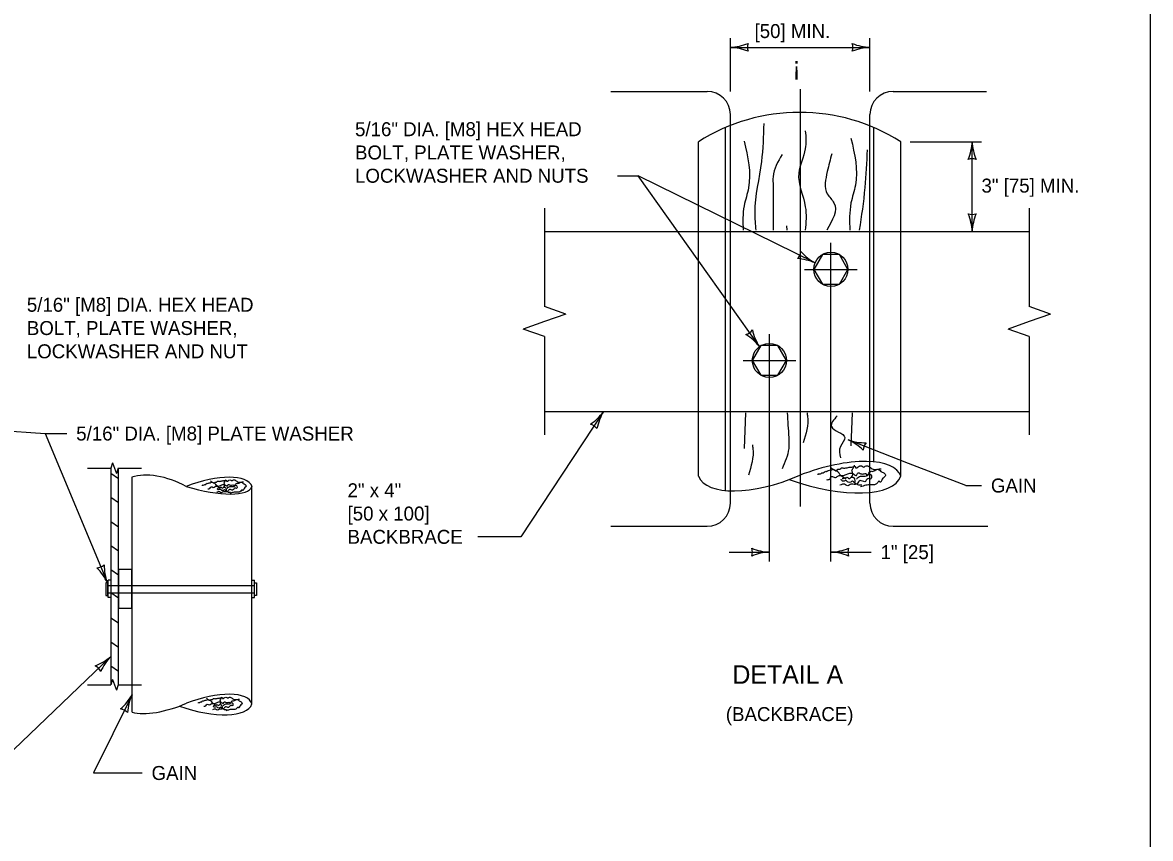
# Model space of a CAD drawing. Extents: x 49991.4 to 50021, y 49987.6 to 50011.4.
# Drawn here: x 50003.769 to 50008.615, y 50003.747 to 50007.252 of the extents above; entities that cross this region are included whole.
import ezdxf

# ---------------------------------------------------------------- set-up
doc = ezdxf.new("R2010")
doc.units = 0
for name, color, linetype in [('Level 1', 7, 'Continuous'), ('Level 2', 7, 'Continuous'), ('Level 3', 7, 'Continuous'), ('Level 4', 7, 'Continuous'), ('Level 5', 7, 'Continuous'), ('Level 6', 7, 'Continuous')]:
    doc.layers.add(name, color=color, linetype=linetype)

msp = doc.modelspace()

# ---------------------------------------------------------------- linework, layer by layer
at = {"layer": 'Level 1'}
for p, q in [((50006.7885, 50006.3548), (50006.7885, 50006.8013)), ((50007.4262, 50006.3548), (50007.4262, 50006.8013)), ((50006.6728, 50006.3548), (50006.6728, 50006.7405)), ((50007.5419, 50006.3548), (50007.5419, 50006.7405)), ((50006.0112, 50006.3548), (50008.0941, 50006.3548)), ((50007.0509, 50006.3792), (50007.0525, 50006.3597)), ((50006.0112, 50005.5805), (50008.0941, 50005.5805)), ((50006.6728, 50005.3029), (50006.6728, 50005.5805)), ((50006.7885, 50005.2434), (50006.7885, 50005.5805)), ((50007.4262, 50005.3653), (50007.4262, 50005.5805)), ((50007.5419, 50005.3029), (50007.5419, 50005.5805)), ((50006.875, 50005.5756), (50006.8691, 50005.4216)), ((50007.3338, 50005.5756), (50007.3281, 50005.4335)), ((50004.1807, 50005.2918), (50004.1482, 50005.3146)), ((50004.1807, 50004.8266), (50004.1807, 50005.3125)), ((50004.2394, 50004.2893), (50004.2394, 50005.2987)), ((50004.7548, 50004.6204), (50004.7548, 50005.2591)), ((50004.1807, 50005.1883), (50004.1482, 50005.2111)), ((50004.1807, 50005.0849), (50004.1482, 50005.1077)), ((50004.1807, 50004.9814), (50004.1482, 50005.0042)), ((50004.181, 50004.8778), (50004.1482, 50004.9008)), ((50004.1363, 50004.7815), (50004.1363, 50004.8567)), ((50004.1468, 50004.8567), (50004.1363, 50004.8567)), ((50004.7548, 50004.8567), (50004.7653, 50004.8567)), ((50004.7653, 50004.7815), (50004.7653, 50004.8567)), ((50004.1468, 50004.7815), (50004.1363, 50004.7815)), ((50004.181, 50004.7792), (50004.1481, 50004.8023)), ((50004.7548, 50004.7815), (50004.7653, 50004.7815)), ((50004.1807, 50004.6711), (50004.1482, 50004.6939)), ((50004.7548, 50004.3245), (50004.7548, 50004.6204)), ((50004.1807, 50004.5676), (50004.1482, 50004.5904)), ((50004.1807, 50004.4642), (50004.1482, 50004.487))]:
    msp.add_line(p, q, dxfattribs=at)
for points in [[(50008.6146, 50011.2628), (50000.3356, 50011.2628), (50000.3356, 50000.0624), (50008.6146, 50000.0624)], [(50007.3153, 50006.1917), (50007.2786, 50006.2554), (50007.2051, 50006.2554), (50007.1683, 50006.1917), (50007.2051, 50006.128), (50007.2786, 50006.128)], [(50007.0513, 50005.8004), (50007.0145, 50005.8641), (50006.9411, 50005.8641), (50006.9043, 50005.8004), (50006.9411, 50005.7367), (50007.0145, 50005.7367)], [(50004.2387, 50004.7369), (50004.2387, 50004.9027), (50004.181, 50004.9027), (50004.181, 50004.7369)], [(50004.1355, 50004.8456), (50004.127, 50004.8456), (50004.127, 50004.791), (50004.1355, 50004.791)], [(50004.7661, 50004.8456), (50004.7746, 50004.8456), (50004.7746, 50004.791), (50004.7661, 50004.791)]]:
    msp.add_lwpolyline(points, close=True, dxfattribs=at)
for points in [[(50004.1481, 50005.3374), (50004.1481, 50004.4066)], [(50004.1807, 50004.4066), (50004.1807, 50005.3374)]]:
    msp.add_lwpolyline(points, dxfattribs=at)
for centre in [(50007.2418, 50006.1917), (50006.9778, 50005.8004)]:
    msp.add_circle(centre, 0.0735, dxfattribs=at)
msp.add_arc((50007.1073, 50006.0536), 0.8128, 57.6815, 122.3185, dxfattribs=at)
for centre, major_axis, ratio, start_param, end_param in [((50007.1627, 50005.16), (0.378, 0.1463), 0.387082, 6.260012, 7.847888), ((50004.4091, 50005.1414), (-0.2192, 0.1177), 0.537084, 4.712389, 5.832893), ((50004.5092, 50005.164), (0.2457, 0.0951), 0.387082, 0, 1.570796), ((50007.0414, 50005.4622), (-0.3686, -0.1593), 0.420526, 0, 1.570796), ((50007.1164, 50005.4533), (0.4255, -0.1504), 0.384401, 4.720139, 6.283185), ((50004.4964, 50005.3379), (0.2585, -0.0788), 0.304673, 4.712389, 6.283185), ((50004.5083, 50004.2318), (0.2457, 0.0951), 0.387082, 6.258968, 7.847526), ((50004.4295, 50004.4282), (-0.2396, -0.1036), 0.420526, 0.495135, 1.570796), ((50004.4783, 50004.4224), (0.2766, -0.0977), 0.384401, 4.720139, 6.281796)]:
    msp.add_ellipse(centre, major_axis=major_axis, ratio=ratio, start_param=start_param, end_param=end_param, dxfattribs=at)
for points in [[(50006.9531, 50006.8184), (50006.9435, 50006.6554), (50006.9148, 50006.4355), (50006.9195, 50006.3597)], [(50006.8691, 50006.7428), (50006.888, 50006.5418), (50006.8691, 50006.4654), (50006.8647, 50006.3597)], [(50007.132, 50006.7867), (50007.132, 50006.71), (50007.1034, 50006.6046), (50007.132, 50006.461), (50007.132, 50006.3597)], [(50007.3281, 50006.755), (50007.3474, 50006.5539), (50007.3281, 50006.4771), (50007.3233, 50006.3597)], [(50007.3974, 50006.7059), (50007.3877, 50006.543), (50007.3639, 50006.3597)], [(50007.0318, 50006.6854), (50006.9935, 50006.5897), (50006.9935, 50006.5515), (50006.9935, 50006.427), (50006.9935, 50006.3597)], [(50007.2455, 50006.6886), (50007.2264, 50006.612), (50007.2264, 50006.5163), (50007.2551, 50006.4779), (50007.2239, 50006.3597)], [(50007.0545, 50005.5756), (50007.0605, 50005.4694), (50007.0605, 50005.4216), (50007.0318, 50005.3355)], [(50007.1394, 50005.5756), (50007.1416, 50005.561), (50007.1226, 50005.4461)], [(50007.2691, 50005.5625), (50007.2443, 50005.5168), (50007.3017, 50005.4689), (50007.2826, 50005.4307), (50007.2826, 50005.3822)], [(50006.9045, 50005.4375), (50006.9067, 50005.4229), (50006.8877, 50005.308)], [(50007.1878, 50005.3084), (50007.1878, 50005.3129), (50007.1967, 50005.3129), (50007.2033, 50005.3173), (50007.21, 50005.3173), (50007.2166, 50005.324), (50007.2233, 50005.324), (50007.2322, 50005.3284), (50007.2388, 50005.3284), (50007.2521, 50005.3328), (50007.2654, 50005.3262), (50007.2721, 50005.3328), (50007.2809, 50005.3328), (50007.2876, 50005.3395), (50007.2987, 50005.3373), (50007.3053, 50005.3395), (50007.312, 50005.3395), (50007.3209, 50005.3417), (50007.3275, 50005.3417), (50007.3364, 50005.3439), (50007.3475, 50005.3439), (50007.3475, 50005.3395), (50007.3541, 50005.3395), (50007.363, 50005.3461), (50007.3763, 50005.3461), (50007.383, 50005.3417), (50007.3896, 50005.3461), (50007.4073, 50005.3439), (50007.4229, 50005.3328), (50007.4406, 50005.3328), (50007.4495, 50005.3306), (50007.4561, 50005.324), (50007.4694, 50005.3173), (50007.4761, 50005.3062), (50007.4739, 50005.3018), (50007.4628, 50005.2907), (50007.4539, 50005.2774), (50007.4495, 50005.2818), (50007.4406, 50005.273), (50007.4295, 50005.2663), (50007.4162, 50005.2663), (50007.3918, 50005.2641), (50007.3697, 50005.2574)], [(50007.3076, 50005.2907), (50007.2809, 50005.3107), (50007.2721, 50005.3218), (50007.2499, 50005.3328), (50007.241, 50005.3417)], [(50007.3297, 50005.2996), (50007.3364, 50005.3151), (50007.332, 50005.3262), (50007.3386, 50005.3395), (50007.343, 50005.3506)], [(50004.542, 50005.2623), (50004.542, 50005.2652), (50004.5478, 50005.2652), (50004.5521, 50005.2681), (50004.5565, 50005.2681), (50004.5608, 50005.2725), (50004.5651, 50005.2725), (50004.5709, 50005.2753), (50004.5752, 50005.2753), (50004.5838, 50005.2782), (50004.5925, 50005.2739), (50004.5968, 50005.2782), (50004.6026, 50005.2782), (50004.6069, 50005.2825), (50004.6141, 50005.2811), (50004.6184, 50005.2825), (50004.6228, 50005.2825), (50004.6286, 50005.284), (50004.6328, 50005.284), (50004.6386, 50005.2854), (50004.6458, 50005.2854), (50004.6458, 50005.2825), (50004.6501, 50005.2825), (50004.6559, 50005.2868), (50004.6646, 50005.2868), (50004.6689, 50005.284), (50004.6732, 50005.2868), (50004.6847, 50005.2854), (50004.6949, 50005.2782), (50004.7064, 50005.2782), (50004.7121, 50005.2767), (50004.7164, 50005.2725), (50004.7251, 50005.2681), (50004.7294, 50005.2609), (50004.728, 50005.258), (50004.7208, 50005.2508), (50004.715, 50005.2422), (50004.7121, 50005.245), (50004.7064, 50005.2393), (50004.6991, 50005.2349), (50004.6905, 50005.2349), (50004.6746, 50005.2335), (50004.6603, 50005.2292)], [(50004.6343, 50005.2566), (50004.6386, 50005.2667), (50004.6358, 50005.2739), (50004.6401, 50005.2825), (50004.6429, 50005.2897)], [(50007.2233, 50005.2885), (50007.2366, 50005.2907), (50007.2455, 50005.3018), (50007.2588, 50005.2974), (50007.2721, 50005.304), (50007.292, 50005.3062), (50007.3076, 50005.3107), (50007.3386, 50005.3129), (50007.3519, 50005.3062), (50007.3586, 50005.3173), (50007.3674, 50005.3151), (50007.3807, 50005.3129), (50007.394, 50005.3129), (50007.3963, 50005.3062), (50007.4051, 50005.3107), (50007.4118, 50005.3107), (50007.4162, 50005.2974), (50007.4118, 50005.2907), (50007.4051, 50005.2929), (50007.3963, 50005.2885), (50007.3874, 50005.2796), (50007.3674, 50005.2841), (50007.3541, 50005.2708), (50007.3364, 50005.2685), (50007.3275, 50005.2685), (50007.3142, 50005.2619), (50007.3009, 50005.2685), (50007.2809, 50005.2641)], [(50007.2898, 50005.2929), (50007.2987, 50005.2951), (50007.3142, 50005.2974), (50007.3186, 50005.2929), (50007.3275, 50005.2974), (50007.3386, 50005.2974), (50007.343, 50005.2752), (50007.3342, 50005.2818), (50007.3275, 50005.2774), (50007.3164, 50005.2774), (50007.3053, 50005.2841), (50007.292, 50005.2818), (50007.2876, 50005.2863), (50007.2854, 50005.2907)], [(50007.3519, 50005.2907), (50007.3608, 50005.2996), (50007.3785, 50005.304), (50007.3985, 50005.3062), (50007.4118, 50005.324), (50007.4207, 50005.324), (50007.4273, 50005.3262), (50007.4428, 50005.3328), (50007.4584, 50005.3351)], [(50004.5651, 50005.2494), (50004.5738, 50005.2508), (50004.5795, 50005.258), (50004.5882, 50005.2552), (50004.5968, 50005.2595), (50004.6098, 50005.2609), (50004.6199, 50005.2638), (50004.6401, 50005.2652), (50004.6487, 50005.2609), (50004.6531, 50005.2681), (50004.6588, 50005.2667), (50004.6674, 50005.2652), (50004.6761, 50005.2652), (50004.6776, 50005.2609), (50004.6833, 50005.2638), (50004.6876, 50005.2638), (50004.6905, 50005.2552), (50004.6876, 50005.2508), (50004.6833, 50005.2522), (50004.6776, 50005.2494), (50004.6718, 50005.2436), (50004.6588, 50005.2465), (50004.6501, 50005.2379), (50004.6386, 50005.2364), (50004.6328, 50005.2364), (50004.6242, 50005.2321), (50004.6156, 50005.2364), (50004.6026, 50005.2335)], [(50004.6199, 50005.2508), (50004.6026, 50005.2638), (50004.5968, 50005.271), (50004.5824, 50005.2782), (50004.5766, 50005.284)], [(50004.6083, 50005.2522), (50004.6141, 50005.2537), (50004.6242, 50005.2552), (50004.6271, 50005.2522), (50004.6328, 50005.2552), (50004.6401, 50005.2552), (50004.6429, 50005.2407), (50004.6372, 50005.245), (50004.6328, 50005.2422), (50004.6256, 50005.2422), (50004.6184, 50005.2465), (50004.6098, 50005.245), (50004.6069, 50005.248), (50004.6055, 50005.2508)], [(50004.6444, 50005.2407), (50004.6545, 50005.2349), (50004.6631, 50005.2349)], [(50004.6487, 50005.2508), (50004.6545, 50005.2566), (50004.666, 50005.2595), (50004.679, 50005.2609), (50004.6876, 50005.2725), (50004.6934, 50005.2725), (50004.6977, 50005.2739), (50004.7078, 50005.2782), (50004.7179, 50005.2797)], [(50007.3453, 50005.2752), (50007.3608, 50005.2663), (50007.3741, 50005.2663)], [(50004.5247, 50004.3283), (50004.5247, 50004.3312), (50004.5305, 50004.3312), (50004.5348, 50004.334), (50004.5391, 50004.334), (50004.5434, 50004.3384), (50004.5478, 50004.3384), (50004.5535, 50004.3413), (50004.5578, 50004.3413), (50004.5665, 50004.3441), (50004.5751, 50004.3398), (50004.5795, 50004.3441), (50004.5852, 50004.3441), (50004.5896, 50004.3485), (50004.5968, 50004.347), (50004.6011, 50004.3485), (50004.6054, 50004.3485), (50004.6112, 50004.3499), (50004.6155, 50004.3499), (50004.6213, 50004.3513), (50004.6285, 50004.3513), (50004.6285, 50004.3485), (50004.6328, 50004.3485), (50004.6386, 50004.3528), (50004.6472, 50004.3528), (50004.6516, 50004.3499), (50004.6559, 50004.3528), (50004.6674, 50004.3513), (50004.6775, 50004.3441), (50004.689, 50004.3441), (50004.6948, 50004.3427), (50004.6991, 50004.3384), (50004.7077, 50004.334), (50004.7121, 50004.3268), (50004.7106, 50004.324), (50004.7034, 50004.3168), (50004.6976, 50004.3081), (50004.6948, 50004.311), (50004.689, 50004.3053), (50004.6818, 50004.3009), (50004.6731, 50004.3009), (50004.6573, 50004.2995), (50004.6429, 50004.2951)], [(50004.5478, 50004.3153), (50004.5564, 50004.3168), (50004.5622, 50004.324), (50004.5708, 50004.3211), (50004.5795, 50004.3254), (50004.5924, 50004.3268), (50004.6026, 50004.3298), (50004.6227, 50004.3312), (50004.6313, 50004.3268), (50004.6357, 50004.334), (50004.6414, 50004.3326), (50004.6501, 50004.3312), (50004.6587, 50004.3312), (50004.6602, 50004.3268), (50004.6659, 50004.3298), (50004.6703, 50004.3298), (50004.6731, 50004.3211), (50004.6703, 50004.3168), (50004.6659, 50004.3182), (50004.6602, 50004.3153), (50004.6544, 50004.3095), (50004.6414, 50004.3125), (50004.6328, 50004.3038), (50004.6213, 50004.3023), (50004.6155, 50004.3023), (50004.6068, 50004.298), (50004.5982, 50004.3023), (50004.5852, 50004.2995)], [(50004.6026, 50004.3168), (50004.5852, 50004.3298), (50004.5795, 50004.337), (50004.5651, 50004.3441), (50004.5593, 50004.3499)], [(50004.591, 50004.3182), (50004.5968, 50004.3196), (50004.6068, 50004.3211), (50004.6097, 50004.3182), (50004.6155, 50004.3211), (50004.6227, 50004.3211), (50004.6256, 50004.3067), (50004.6198, 50004.311), (50004.6155, 50004.3081), (50004.6083, 50004.3081), (50004.6011, 50004.3125), (50004.5924, 50004.311), (50004.5896, 50004.3139), (50004.5881, 50004.3168)], [(50004.6169, 50004.3225), (50004.6213, 50004.3326), (50004.6184, 50004.3398), (50004.6227, 50004.3485), (50004.6256, 50004.3557)], [(50004.6313, 50004.3168), (50004.6371, 50004.3225), (50004.6486, 50004.3254), (50004.6616, 50004.3268), (50004.6703, 50004.3384), (50004.6761, 50004.3384), (50004.6804, 50004.3398), (50004.6904, 50004.3441), (50004.7006, 50004.3456)], [(50004.6271, 50004.3067), (50004.6371, 50004.3009), (50004.6458, 50004.3009)]]:
    msp.add_spline(points, degree=3, dxfattribs=at)
at = {"layer": 'Level 3'}
for p, q in [((50006.81, 50006.9566), (50006.81, 50007.1858)), ((50007.4096, 50006.9566), (50007.4096, 50007.1858)), ((50006.81, 50007.1458), (50007.4096, 50007.1458)), ((50007.5819, 50006.7405), (50007.8887, 50006.7405)), ((50007.8487, 50006.3629), (50007.8487, 50006.7405)), ((50006.3253, 50006.5941), (50006.4135, 50006.5941)), ((50007.1738, 50006.2195), (50006.4135, 50006.5941)), ((50006.9347, 50005.8599), (50006.4135, 50006.5941)), ((50006.2647, 50005.5805), (50005.9099, 50005.0427)), ((50003.0917, 50005.541), (50003.8659, 50005.4865)), ((50003.8659, 50005.4865), (50004.1336, 50004.8456)), ((50003.8659, 50005.4865), (50003.9597, 50005.4865)), ((50007.5759, 50005.3582), (50007.3157, 50005.4588)), ((50007.8217, 50005.2631), (50007.5759, 50005.3582)), ((50007.8217, 50005.2631), (50007.8892, 50005.2631)), ((50005.9099, 50005.0427), (50005.7253, 50005.0427)), ((50006.8044, 50004.977), (50006.9778, 50004.977)), ((50007.2418, 50004.977), (50007.4152, 50004.977)), ((50004.1481, 50004.5291), (50003.606, 50004.0087)), ((50004.2394, 50004.3634), (50004.0735, 50004.0281)), ((50004.0735, 50004.028), (50004.2834, 50004.028))]:
    msp.add_line(p, q, dxfattribs=at)
for centre, radius, start, end in [((50006.7985, 50007.3785), 0.233, 272.8273, 292.0772), ((50006.8008, 50006.9237), 0.2223, 67.456, 87.6395), ((50006.9382, 50007.1458), 0.0548, 162.1388, 197.8612), ((50007.4188, 50007.3679), 0.2223, 247.456, 267.6395), ((50007.2814, 50007.1458), 0.0548, 342.1388, 17.8612), ((50007.4211, 50006.9131), 0.233, 92.8273, 112.0772), ((50007.6266, 50006.7497), 0.2223, 337.456, 357.6395), ((50008.0814, 50006.752), 0.233, 182.8273, 202.0772), ((50007.8487, 50006.6123), 0.0548, 72.1388, 107.8612), ((50007.8487, 50006.483), 0.0548, 252.1388, 287.8612), ((50007.616, 50006.3433), 0.233, 2.8273, 22.0772), ((50008.0709, 50006.3456), 0.2223, 157.456, 177.6395), ((50007.0587, 50006.2762), 0.0548, 315.908, 351.6304), ((50007.2802, 50006.4147), 0.2223, 221.2252, 241.4087), ((50007.0812, 50006.0057), 0.233, 66.5965, 85.8464), ((50006.8605, 50005.9645), 0.0548, 287.5099, 323.2322), ((50007.1211, 50005.9811), 0.2223, 192.8271, 213.0106), ((50006.7516, 50005.7159), 0.233, 38.1984, 57.4482), ((50006.0844, 50005.7105), 0.2223, 304.0435, 324.227), ((50006.4653, 50005.4619), 0.233, 149.4148, 168.6646), ((50006.1941, 50005.4735), 0.0548, 38.7263, 74.4486), ((50007.227, 50005.2549), 0.2223, 46.3085, 66.492), ((50007.3889, 50005.68), 0.233, 251.6798, 270.9296), ((50007.4353, 50005.4125), 0.0548, 140.9913, 176.7137), ((50006.987, 50005.1991), 0.2223, 247.456, 267.6395), ((50006.8496, 50004.977), 0.0548, 342.1388, 17.8612), ((50006.9893, 50004.7443), 0.233, 92.8273, 112.0772), ((50007.2303, 50005.2097), 0.233, 272.8273, 292.0772), ((50007.2326, 50004.7549), 0.2223, 67.456, 87.6395), ((50007.37, 50004.977), 0.0548, 162.1388, 197.8612), ((50004.0842, 50004.9639), 0.0548, 274.8073, 310.5297), ((50003.9233, 50004.7453), 0.233, 25.4958, 44.7456), ((50004.3421, 50004.9228), 0.2223, 180.1245, 200.308), ((50004.0009, 50004.6957), 0.2223, 291.286, 311.4695), ((50004.3175, 50004.3692), 0.233, 136.6573, 155.9071), ((50004.0556, 50004.4403), 0.0548, 25.9688, 61.6912), ((50004.0458, 50004.4728), 0.2223, 310.3488, 330.5324), ((50004.4518, 50004.2676), 0.233, 155.7201, 174.97), ((50004.181, 50004.2493), 0.0548, 45.0316, 80.754)]:
    msp.add_arc(centre, radius, start, end, dxfattribs=at)
at = {"layer": 'Level 4'}
for p, q in [((50006.2966, 50006.9566), (50006.71, 50006.9566)), ((50007.5096, 50006.9566), (50007.9101, 50006.9566)), ((50006.81, 50005.1879), (50006.81, 50006.8566)), ((50007.4096, 50005.1879), (50007.4096, 50006.8566)), ((50006.6728, 50005.5805), (50006.6728, 50006.3548)), ((50006.7885, 50005.5805), (50006.7885, 50006.3548)), ((50007.4262, 50005.5805), (50007.4262, 50006.3548)), ((50007.5419, 50005.5805), (50007.5419, 50006.3548)), ((50006.2966, 50005.0879), (50006.71, 50005.0879)), ((50007.5096, 50005.0879), (50007.9163, 50005.0879)), ((50004.1352, 50004.8334), (50004.7653, 50004.8334)), ((50004.1363, 50004.8019), (50004.7653, 50004.8019))]:
    msp.add_line(p, q, dxfattribs=at)
for centre, start, end in [((50006.71, 50006.8566), 0, 90), ((50007.5096, 50006.8566), 90, 180), ((50006.71, 50005.1879), 270, 0), ((50007.5096, 50005.1879), 180, 270)]:
    msp.add_arc(centre, 0.1, start, end, dxfattribs=at)
at = {"layer": 'Level 5'}
for p, q in [((50007.1098, 50006.9664), (50007.1098, 50005.1729)), ((50007.2418, 50004.937), (50007.2418, 50006.3052)), ((50007.1283, 50006.1917), (50007.3553, 50006.1917)), ((50006.9778, 50004.937), (50006.9778, 50005.9139)), ((50006.8643, 50005.8004), (50007.0913, 50005.8004))]:
    msp.add_line(p, q, dxfattribs=at)
at = {"layer": 'Level 6'}
for p, q in [((50006.0112, 50006.4548), (50006.0112, 50006.0325)), ((50008.0941, 50006.4548), (50008.0941, 50006.0325)), ((50006.1026, 50006.0001), (50006.0112, 50006.0325)), ((50008.1855, 50006.0001), (50008.0941, 50006.0325)), ((50006.0112, 50005.9677), (50005.9198, 50005.9353)), ((50006.1026, 50006.0001), (50006.0112, 50005.9677)), ((50008.0941, 50005.9677), (50008.0027, 50005.9353)), ((50008.1855, 50006.0001), (50008.0941, 50005.9677)), ((50006.0112, 50005.9029), (50005.9198, 50005.9353)), ((50008.0941, 50005.9029), (50008.0027, 50005.9353)), ((50006.0112, 50005.9029), (50006.0112, 50005.4805)), ((50008.0941, 50005.9029), (50008.0941, 50005.4805)), ((50004.0481, 50005.3374), (50004.1482, 50005.3374)), ((50004.1563, 50005.3602), (50004.1482, 50005.3374)), ((50004.1563, 50005.3602), (50004.1644, 50005.3374)), ((50004.1644, 50005.3374), (50004.1725, 50005.3146)), ((50004.1806, 50005.3374), (50004.1725, 50005.3146)), ((50004.1806, 50005.3374), (50004.2807, 50005.3374)), ((50004.1563, 50004.4294), (50004.1482, 50004.4066)), ((50004.1563, 50004.4294), (50004.1644, 50004.4066)), ((50004.0481, 50004.4066), (50004.1482, 50004.4066)), ((50004.1644, 50004.4066), (50004.1725, 50004.3838)), ((50004.1806, 50004.4066), (50004.1725, 50004.3838)), ((50004.1806, 50004.4066), (50004.2807, 50004.4066))]:
    msp.add_line(p, q, dxfattribs=at)

# ---------------------------------------------------------------- texts
at = {"layer": 'Level 2'}
for s, height, p in [('[50] MIN.', 0.06, (50006.9137, 50007.1858)), ('¡', 0.0799, (50007.0764, 50007.0259)), ('5/16" DIA. [M8] HEX HEAD', 0.06, (50005.1975, 50006.7641)), ('BOLT, PLATE WASHER, ', 0.06, (50005.1975, 50006.6641)), ('LOCKWASHER AND NUTS', 0.06, (50005.1975, 50006.5641)), ('3" [75] MIN.', 0.06, (50007.8887, 50006.5217)), ('5/16" [M8] DIA. HEX HEAD', 0.06, (50003.7876, 50006.0098)), ('BOLT, PLATE WASHER,', 0.06, (50003.7876, 50005.9098)), ('LOCKWASHER AND NUT', 0.06, (50003.7876, 50005.8098)), ('5/16" DIA. [M8] PLATE WASHER', 0.06, (50003.9997, 50005.4565)), ('GAIN', 0.06, (50007.9292, 50005.2331)), ('2" x 4"', 0.06, (50005.1653, 50005.2127)), ('[50 x 100]', 0.06, (50005.1653, 50005.1127)), ('BACKBRACE', 0.06, (50005.1653, 50005.0127)), ('1" [25]', 0.06, (50007.4552, 50004.947)), ('DETAIL A', 0.08, (50006.8188, 50004.4111)), ('(BACKBRACE)', 0.06, (50006.7905, 50004.2511)), ('GAIN', 0.06, (50004.3234, 50003.998))]:
    msp.add_text(s, height=height, dxfattribs=at).set_placement(p)

doc.saveas('drawing.dxf')
